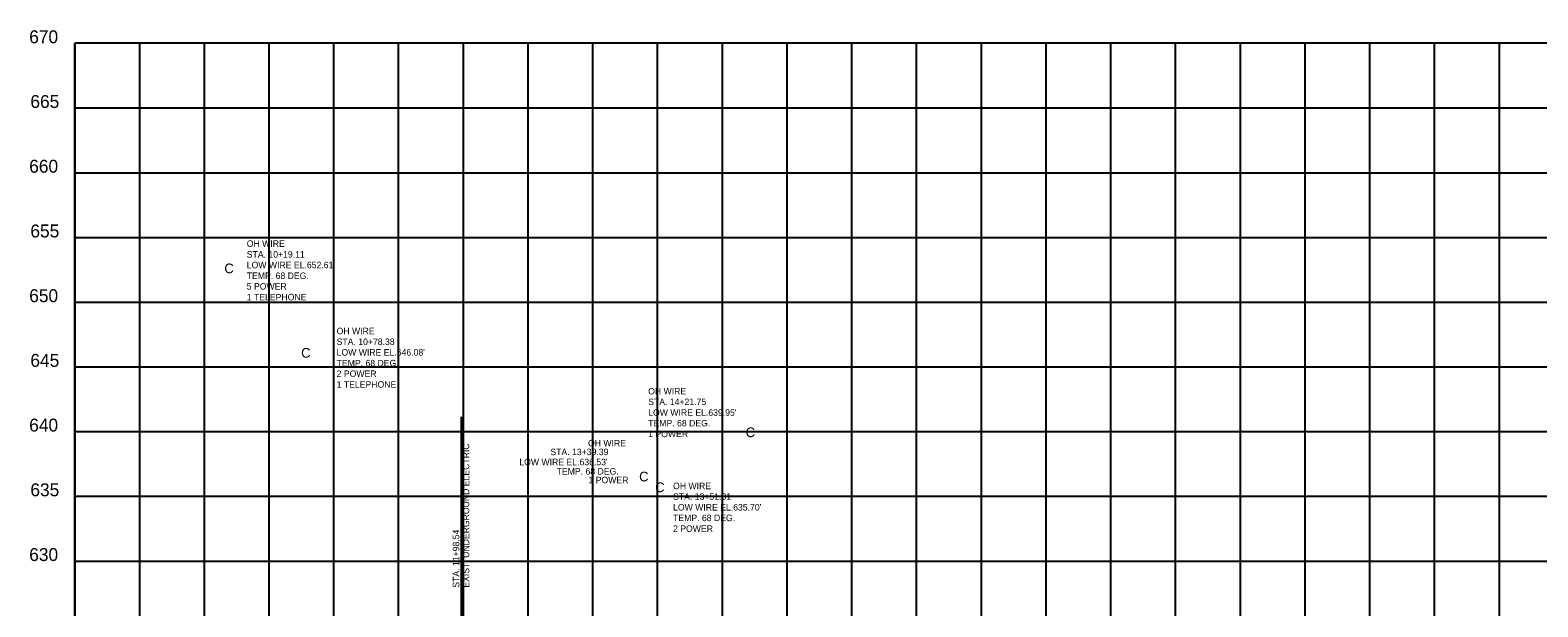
# Model space of a CAD drawing. Extents: x 1729869 to 1735532, y 648588 to 653771.
# Drawn here: x 1732068 to 1733232, y 649554 to 649999 of the extents above; entities that cross this region are included whole.
import ezdxf

# ---------------------------------------------------------------- set-up
doc = ezdxf.new("R2010")
doc.units = 0
for name, color, linetype in [('DESIGN - SHEET - Corner Text', 7, 'Continuous'), ('DESIGN - SHEET - Light Grid', 7, 'Continuous'), ('SURVEY - PROFILE - Utilities - Electric with Text', 7, 'Continuous'), ('SURVEY - PROFILE - Utilities - Overhead Wire Crossings', 7, 'Continuous')]:
    doc.layers.add(name, color=color, linetype=linetype)

msp = doc.modelspace()

# ---------------------------------------------------------------- linework, layer by layer
at = {"layer": 'DESIGN - SHEET - Light Grid'}
for p, q in [((1732102.2, 648689.3), (1732102.2, 649989.3)), ((1735502.2, 649989.3), (1732102.2, 649989.3)), ((1732102.2, 649989.3), (1732102.2, 648689.3)), ((1732152.2, 648689.3), (1732152.2, 649989.3)), ((1732202.2, 648689.3), (1732202.2, 649989.3)), ((1732252.2, 648689.3), (1732252.2, 649989.3)), ((1732302.2, 648689.3), (1732302.2, 649989.3)), ((1732352.2, 648689.3), (1732352.2, 649989.3)), ((1732402.2, 648689.3), (1732402.2, 649989.3)), ((1732452.2, 648689.3), (1732452.2, 649989.3)), ((1732502.2, 648689.3), (1732502.2, 649989.3)), ((1732552.2, 648689.3), (1732552.2, 649989.3)), ((1732602.2, 648689.3), (1732602.2, 649989.3)), ((1732652.2, 648689.3), (1732652.2, 649989.3)), ((1732702.2, 648689.3), (1732702.2, 649989.3)), ((1732752.2, 648689.3), (1732752.2, 649989.3)), ((1732802.2, 648689.3), (1732802.2, 649989.3)), ((1732852.2, 648689.3), (1732852.2, 649989.3)), ((1732902.2, 648689.3), (1732902.2, 649989.3)), ((1732952.2, 648689.3), (1732952.2, 649989.3)), ((1733002.2, 648689.3), (1733002.2, 649989.3)), ((1733052.2, 648689.3), (1733052.2, 649989.3)), ((1733102.2, 648689.3), (1733102.2, 649989.3)), ((1733152.2, 648689.3), (1733152.2, 649989.3)), ((1733202.2, 648689.3), (1733202.2, 649989.3)), ((1732102.2, 649939.3), (1735502.2, 649939.3)), ((1732102.2, 649889.3), (1735502.2, 649889.3)), ((1732102.2, 649839.3), (1735502.2, 649839.3)), ((1732102.2, 649789.3), (1735502.2, 649789.3)), ((1732102.2, 649739.3), (1735502.2, 649739.3)), ((1732102.2, 649689.3), (1735502.2, 649689.3)), ((1732102.2, 649639.3), (1735502.2, 649639.3)), ((1732102.2, 649589.3), (1735502.2, 649589.3))]:
    msp.add_line(p, q, dxfattribs=at)
at = {"layer": 'SURVEY - PROFILE - Utilities - Electric with Text'}
msp.add_line((1732400.8, 649500.8), (1732400.8, 649700.7), dxfattribs=at)

# ---------------------------------------------------------------- texts
at = {"layer": 'DESIGN - SHEET - Corner Text'}
for s, p in [('670', (1732066.9, 649989.3)), ('665', (1732067.8, 649939.3)), ('660', (1732066.9, 649889.3)), ('655', (1732067.8, 649839.3)), ('650', (1732066.9, 649789.3)), ('645', (1732067.8, 649739.3)), ('640', (1732066.9, 649689.3)), ('635', (1732067.8, 649639.3)), ('630', (1732066.9, 649589.3))]:
    msp.add_text(s, height=10, dxfattribs=at).set_placement(p)
at = {"layer": 'SURVEY - PROFILE - Utilities - Electric with Text'}
for s, p in [('EXIST. UNDERGROUND ELECTRIC', (1732406.7, 649568.7)), ('STA. 11+98.54', (1732399, 649568.7))]:
    msp.add_text(s, height=5, rotation=90, dxfattribs=at).set_placement(p)
at = {"layer": 'SURVEY - PROFILE - Utilities - Overhead Wire Crossings'}
for s, height, p in [('OH WIRE', 5, (1732234.9, 649832)), ('STA. 10+19.11', 5, (1732234.9, 649823.7)), ('C', 7.5, (1732217.6, 649811.6)), ("LOW WIRE EL.652.61'", 5, (1732234.9, 649815.5)), ('TEMP. 68 DEG.', 5, (1732234.9, 649807.2)), ('5 POWER', 5, (1732234.9, 649799)), ('1 TELEPHONE', 5, (1732234.9, 649790.7)), ('OH WIRE', 5, (1732304.3, 649764.5)), ('STA. 10+78.38', 5, (1732304.3, 649756.2)), ('C', 7.5, (1732276.9, 649746.4)), ('TEMP. 68 DEG.', 5, (1732304.3, 649739.7)), ("LOW WIRE EL.646.08'", 5, (1732304.3, 649748)), ('2 POWER', 5, (1732304.3, 649731.5)), ('1 TELEPHONE', 5, (1732304.3, 649723.2)), ('OH WIRE', 5, (1732544.9, 649718)), ('STA. 14+21.75', 5, (1732544.9, 649709.8)), ('TEMP. 68 DEG.', 5, (1732544.9, 649693.3)), ("LOW WIRE EL.639.95'", 5, (1732544.9, 649701.5)), ('1 POWER', 5, (1732544.9, 649685)), ('C', 7.5, (1732620.2, 649685)), ('STA. 13+39.39', 5, (1732469.4, 649671.1)), ('OH WIRE', 5, (1732498.4, 649677.9)), ("LOW WIRE EL.636.53'", 5, (1732445.4, 649663.3)), ('TEMP. 68 DEG.', 5, (1732474.2, 649656.1)), ('1 POWER', 5, (1732498.8, 649649.4)), ('C', 7.5, (1732537.9, 649650.8)), ('C', 7.5, (1732550.3, 649642.5)), ('OH WIRE', 5, (1732564.1, 649644.8)), ('STA. 13+51.81', 5, (1732564.1, 649636.6)), ("LOW WIRE EL.635.70'", 5, (1732564.1, 649628.3)), ('TEMP. 68 DEG.', 5, (1732564.1, 649620.1)), ('2 POWER', 5, (1732564.1, 649611.8))]:
    msp.add_text(s, height=height, dxfattribs=at).set_placement(p)

doc.saveas('drawing.dxf')
